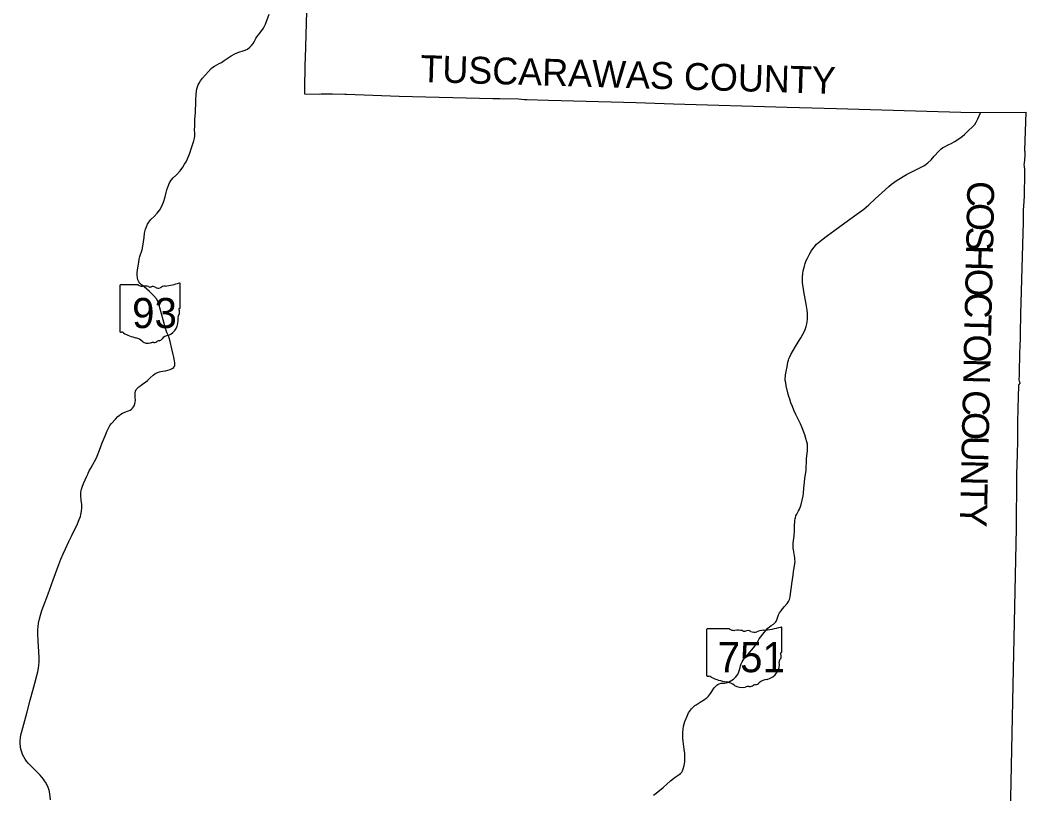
# Model space of a CAD drawing. Extents: x 2004415 to 2276415, y 751181 to 927181.
# Drawn here: x 2177346 to 2214759, y 838414 to 867212 of the extents above; entities that cross this region are included whole.
import ezdxf

# ---------------------------------------------------------------- set-up
doc = ezdxf.new("R2010")
doc.units = 0
for name, color, linetype in [('GM_X_County', 7, 'Continuous'), ('GM_X_County_Text', 7, 'Continuous'), ('GM_X_State_Location', 7, 'Continuous'), ('GM_X_State_Route', 7, 'Continuous'), ('GM_X_State_Shield', 7, 'Continuous')]:
    doc.layers.add(name, color=color, linetype=linetype)

msp = doc.modelspace()

# ---------------------------------------------------------------- linework, layer by layer
at = {"layer": 'GM_X_County'}
msp.add_lwpolyline([(2188009, 867975), (2187946, 865793), (2187943, 865563), (2187924, 864631), (2187921, 864465), (2188480, 864451), (2188549, 864467), (2188971, 864466), (2189427, 864451), (2189489, 864451), (2191444, 864380), (2194934, 864291), (2195070, 864290), (2195195, 864289), (2195884, 864276), (2196109, 864261), (2196154, 864260), (2196195, 864259), (2196999, 864238), (2200266, 864143), (2201652, 864100), (2205881, 863975), (2207719, 863920), (2212337, 863781), (2213068, 863770), (2214759, 863787), (2214712, 862361), (2214713, 862356), (2214726, 862318), (2214720, 862172), (2214712, 862011), (2214697, 861892), (2214689, 861834), (2214694, 861764), (2214704, 861652), (2214711, 861298), (2214695, 860899), (2214692, 860688), (2214680, 860444), (2214670, 860308), (2214664, 860127), (2214654, 860032), (2214655, 859699), (2214553, 856272), (2214557, 856218), (2214550, 855598), (2214546, 855462), (2214541, 855352), (2214528, 855120), (2214520, 854788), (2214518, 854552), (2214507, 854329), (2214505, 854132), (2214511, 853994), (2214501, 853822), (2214513, 853771), (2214537, 853723), (2214530, 853697), (2214491, 853649), (2214483, 853607), (2214483, 853542), (2214483, 853506), (2214474, 853287), (2214468, 853109), (2214458, 852828), (2214455, 852617), (2214452, 852373), (2214451, 852227), (2214446, 852103), (2214442, 851561), (2214438, 851040), (2214411, 850311), (2214412, 850218), (2214393, 848301), (2214324, 844793), (2214279, 842459), (2214173, 837662)], dxfattribs=at)
at = {"layer": 'GM_X_State_Route'}
for points in [[(2183864, 863756), (2183871, 863833), (2183883, 864126), (2183887, 864262), (2183894, 864435), (2183908, 864562), (2183925, 864659), (2183945, 864734), (2183972, 864808), (2184007, 864870), (2184055, 864947), (2184134, 865056), (2184349, 865304), (2184449, 865409), (2184513, 865461), (2184573, 865499), (2184662, 865547), (2184755, 865591), (2184832, 865635), (2184933, 865704), (2185086, 865812), (2185202, 865886), (2185332, 865958), (2185417, 865998), (2185507, 866033), (2185608, 866058), (2185713, 866092), (2185800, 866131), (2185894, 866199), (2185959, 866270), (2186018, 866346), (2186062, 866424), (2186114, 866525), (2186155, 866590), (2186213, 866662), (2186342, 866821), (2186405, 866913), (2186472, 867060), (2186526, 867197), (2186612, 867437)], [(2183067, 854300), (2183098, 854341), (2183103, 854383), (2183101, 854453), (2183090, 854535), (2183069, 854663), (2183044, 854772), (2182991, 854982), (2182931, 855250), (2182886, 855386), (2182848, 855481), (2182802, 855583), (2182757, 855733), (2182669, 856056), (2182609, 856277), (2182549, 856505), (2182505, 856671), (2182473, 856755), (2182420, 856838), (2182323, 856950), (2182156, 857116), (2182058, 857204), (2181965, 857282), (2181865, 857359), (2181801, 857418), (2181758, 857468), (2181726, 857547), (2181708, 857623), (2181698, 857715), (2181702, 857820), (2181724, 857991), (2181744, 858129), (2181757, 858205), (2181779, 858314), (2181805, 858410), (2181883, 858664), (2181912, 858795), (2181935, 858956), (2181955, 859118), (2181978, 859278), (2182010, 859428), (2182043, 859521), (2182088, 859613), (2182139, 859698), (2182211, 859787), (2182330, 859903), (2182448, 860027), (2182543, 860150), (2182605, 860259), (2182683, 860434), (2182743, 860635), (2182782, 860799), (2182805, 860896), (2182837, 861000), (2182875, 861095), (2182905, 861161), (2182968, 861252), (2183039, 861336), (2183160, 861458), (2183300, 861607), (2183401, 861739), (2183466, 861847), (2183521, 861939), (2183573, 862052), (2183654, 862259), (2183725, 862457), (2183811, 862718), (2183833, 862816), (2183842, 862901), (2183843, 862989), (2183839, 863139), (2183841, 863250), (2183844, 863411), (2183847, 863527), (2183864, 863756)], [(2200908, 838368), (2201005, 838441), (2201263, 838656), (2201538, 838895), (2201654, 838991), (2201716, 839036), (2201865, 839132), (2201914, 839171), (2201955, 839217), (2201989, 839275), (2202016, 839349), (2202046, 839466), (2202068, 839612), (2202077, 839726), (2202076, 839813), (2202069, 839913), (2202046, 840083), (2202010, 840372), (2201999, 840489), (2201998, 840608), (2202001, 840714), (2202012, 840810), (2202029, 840931), (2202051, 841024), (2202078, 841110), (2202158, 841311), (2202215, 841427), (2202247, 841478), (2202284, 841534), (2202322, 841584), (2202389, 841652), (2202448, 841702), (2202492, 841731), (2202646, 841823), (2202809, 841927), (2202866, 841971), (2202901, 842000), (2202952, 842052), (2203024, 842154), (2203164, 842362), (2203212, 842416), (2203259, 842457), (2203297, 842483), (2203351, 842509), (2203429, 842529), (2203486, 842531), (2203546, 842537), (2203605, 842546), (2203664, 842565), (2203756, 842604), (2203883, 842685), (2203934, 842728), (2203970, 842771), (2204020, 842834), (2204054, 842888), (2204098, 842996), (2204130, 843119), (2204161, 843225), (2204204, 843323), (2204246, 843395), (2204296, 843467), (2204410, 843603), (2204632, 843855), (2204718, 843956), (2204748, 843997), (2204781, 844049), (2204806, 844105), (2204842, 844183), (2204884, 844251), (2204968, 844353), (2205086, 844491), (2205166, 844579), (2205225, 844633), (2205281, 844676), (2205368, 844734), (2205421, 844778), (2205454, 844812), (2205483, 844858), (2205511, 844925), (2205538, 845002), (2205563, 845079), (2205600, 845156), (2205650, 845230), (2205711, 845306), (2205783, 845389), (2205880, 845499), (2205932, 845573), (2205967, 845652), (2205994, 845753), (2206007, 845856), (2206041, 846115), (2206055, 846228), (2206099, 846554), (2206119, 846694), (2206151, 846900), (2206164, 846992), (2206171, 847070), (2206170, 847126), (2206163, 847200), (2206149, 847277), (2206114, 847502), (2206107, 847565), (2206102, 847646), (2206107, 847730), (2206121, 847850), (2206137, 848003), (2206147, 848226), (2206156, 848464), (2206159, 848508), (2206165, 848599), (2206172, 848648), (2206185, 848694), (2206204, 848757), (2206234, 848820), (2206278, 848902), (2206303, 848949), (2206332, 849010), (2206374, 849113), (2206397, 849186), (2206438, 849345), (2206469, 849504), (2206482, 849603), (2206501, 849789), (2206521, 850010), (2206540, 850154), (2206576, 850392), (2206582, 850454), (2206588, 850562), (2206596, 850786), (2206601, 850901), (2206638, 851181), (2206641, 851284), (2206638, 851362), (2206630, 851427), (2206611, 851519), (2206576, 851643), (2206531, 851779), (2206435, 852036), (2206371, 852187), (2206313, 852311), (2206204, 852540), (2206129, 852698), (2206073, 852827), (2206020, 852968), (2205973, 853102), (2205941, 853198), (2205916, 853288), (2205844, 853606), (2205824, 853714), (2205810, 853802), (2205810, 853882), (2205814, 853943), (2205822, 854014), (2205845, 854131), (2205878, 854307), (2205908, 854482), (2205924, 854556), (2205939, 854604), (2205964, 854659), (2206018, 854761), (2206194, 855069), (2206391, 855391), (2206455, 855504), (2206507, 855606), (2206547, 855703), (2206583, 855814), (2206606, 855902), (2206620, 855986), (2206634, 856086), (2206639, 856188), (2206634, 856309), (2206623, 856414), (2206587, 856635), (2206534, 856911), (2206511, 857035), (2206482, 857196), (2206460, 857359), (2206452, 857450), (2206449, 857556), (2206451, 857641), (2206462, 857783), (2206480, 857880), (2206496, 857967), (2206519, 858052), (2206549, 858153), (2206589, 858259), (2206631, 858357), (2206667, 858431), (2206722, 858529), (2206775, 858614), (2206835, 858697), (2206886, 858761), (2206976, 858869), (2207094, 858978), (2207166, 859039), (2207374, 859193), (2207647, 859390), (2207975, 859630), (2208155, 859761), (2208471, 859985), (2208729, 860181), (2208916, 860341), (2209158, 860562), (2209401, 860779), (2209663, 861016), (2209758, 861100), (2209842, 861164), (2209975, 861253), (2210323, 861460), (2210587, 861602), (2210965, 861794), (2211054, 861849), (2211115, 861900), (2211236, 862015), (2211353, 862143), (2211518, 862337), (2211602, 862422), (2211657, 862458), (2211728, 862500), (2211871, 862569), (2211978, 862623), (2212114, 862698), (2212204, 862751), (2212336, 862846), (2212471, 862959), (2212642, 863116), (2212757, 863229), (2212856, 863331), (2212911, 863412), (2212978, 863540), (2213069, 863767)], [(2179609, 849649), (2179614, 849692), (2179626, 849755), (2179651, 849835), (2179704, 849966), (2179764, 850101), (2179831, 850242), (2179873, 850336), (2179881, 850354), (2179919, 850439), (2179980, 850540), (2180055, 850667), (2180159, 850870), (2180213, 850982), (2180298, 851212), (2180401, 851481), (2180508, 851746), (2180584, 851922), (2180643, 852044), (2180687, 852122), (2180742, 852200), (2180893, 852365), (2180978, 852454), (2181029, 852501), (2181096, 852550), (2181158, 852586), (2181236, 852623), (2181381, 852674), (2181434, 852698), (2181485, 852727), (2181532, 852768), (2181570, 852820), (2181591, 852854), (2181616, 852928), (2181631, 852991), (2181636, 853063), (2181630, 853163), (2181626, 853267), (2181627, 853345), (2181642, 853408), (2181666, 853464), (2181708, 853516), (2181758, 853560), (2181831, 853617), (2181917, 853676), (2182012, 853740), (2182090, 853803), (2182188, 853901), (2182292, 853996), (2182360, 854048), (2182454, 854096), (2182526, 854120), (2182582, 854135), (2182734, 854160)], [(2182734, 854160), (2182749, 854163), (2182845, 854184), (2182928, 854210), (2182999, 854245), (2183058, 854288), (2183067, 854300)], [(2178479, 838195), (2178449, 838422), (2178421, 838548), (2178391, 838646), (2178343, 838761), (2178290, 838854), (2178259, 838901), (2178216, 838960), (2178154, 839037), (2178091, 839107), (2177964, 839237), (2177776, 839425), (2177648, 839562), (2177589, 839632), (2177537, 839707), (2177484, 839796), (2177441, 839884), (2177410, 839966), (2177376, 840079), (2177359, 840166), (2177346, 840308), (2177350, 840407), (2177358, 840496), (2177377, 840610), (2177407, 840742), (2177592, 841418), (2177724, 841906), (2177896, 842537), (2177973, 842823), (2178006, 842959), (2178029, 843092), (2178043, 843203), (2178052, 843331), (2178055, 843489), (2178042, 843699), (2178015, 844116), (2178003, 844378), (2178004, 844525), (2178015, 844644), (2178032, 844770), (2178064, 844932), (2178099, 845061), (2178157, 845234), (2178276, 845559), (2178387, 845860), (2178576, 846378), (2178752, 846853), (2178866, 847148), (2178950, 847343), (2179035, 847534), (2179160, 847804), (2179268, 848034), (2179476, 848463), (2179546, 848625), (2179588, 848742), (2179608, 848815), (2179628, 848918), (2179637, 849069), (2179636, 849184), (2179621, 849342), (2179606, 849525), (2179605, 849612), (2179609, 849649)]]:
    msp.add_lwpolyline(points, dxfattribs=at)
at = {"layer": 'GM_X_State_Shield'}
for p, q in [((2181056, 857331), (2181056, 855630)), ((2181735, 857361), (2181078, 857361)), ((2183298, 856513), (2183298, 857403)), ((2183297, 856513), (2183298, 856513)), ((2202880, 844524), (2202880, 842823)), ((2203728, 844553), (2202907, 844553)), ((2205681, 843705), (2205681, 844595)), ((2205681, 843706), (2205681, 843705))]:
    msp.add_line(p, q, dxfattribs=at)
for centre, radius, start, end in [((2181082, 857335), 26, 98.1301, 188.1301), ((2181891, 857558), 252, 231.6195, 271.1119), ((2181975, 856406), 904, 80.4867, 94.9883), ((2182180, 857344), 72.7, 219.7921, 297.1024), ((2182287, 857147), 151, 54.4667, 119.1411), ((2182482, 857417), 182, 233.8562, 294.8282), ((2182802, 856841), 478, 97.3462, 120.7689), ((2182499, 859680), 2377, 275.8445, 288.9065), ((2183273, 857406), 25, 351.8621, 97.738), ((2183292, 856448), 38.6, 107.944, 210.337), ((2183046, 856335), 232, 340.033, 23.6496), ((2183271, 856509), 26.7, 289.6038, 7.7341), ((2182632, 856027), 595, 292.3089, 8.9858), ((2183387, 856140), 169, 136.8065, 186.9296), ((2181082, 855626), 26.2, 171.9584, 258.3066), ((2181086, 855800), 200, 267.339, 280.6039), ((2181127, 855532), 72.1, 29.7484, 93.2717), ((2182037, 857060), 1716, 240.4129, 257.1985), ((2181525, 854866), 537, 47.1842, 75.836), ((2182328, 855396), 182, 268.777, 315.5493), ((2182492, 855231), 51.1, 65.7517, 132.6484), ((2182471, 855465), 192, 282.8732, 323.2771), ((2182883, 855153), 326, 94.4031, 142.5768), ((2182106, 855524), 341, 230.7004, 286.2918), ((2182303, 854935), 280, 85.6951, 111.2099)]:
    msp.add_arc(centre, radius, start, end, dxfattribs=at)
for centre, major_axis, start_param, end_param in [((2202912, 844527), (32.5, 0), 1.712693, 3.28349), ((2203923, 844751), (315, 0), 4.042523, 4.731795), ((2204028, 843598), (1130, 0), 1.404758, 1.657858), ((2204284, 844536), (90.8, 0), 3.836095, 5.185415), ((2204417, 844340), (189, 0), 0.950623, 2.079405), ((2204661, 844609), (227, 0), 4.081561, 5.145723), ((2205062, 844034), (598, 0), 1.699011, 2.107814), ((2204683, 846872), (2971, 0), 4.814394, 5.042369), ((2205650, 844599), (31.2, 0), 6.141152, 7.989035), ((2205674, 843640), (48.3, 0), 1.883978, 3.671073), ((2205648, 843702), (33.4, 0), 5.05454, 6.418171), ((2204850, 843220), (743, 0), 5.101752, 6.440018), ((2205793, 843333), (211, 0), 2.387724, 3.262537), ((2205367, 843528), (290, 0), 5.934695, 6.695948), ((2202912, 842819), (32.7, 0), 3.00124, 4.508301), ((2202917, 842993), (250, 0), 4.665946, 4.897461), ((2202968, 842725), (90.1, 0), 0.519207, 1.627899), ((2204106, 844253), (2146, 0), 4.195997, 4.488961), ((2203466, 842058), (671, 0), 0.823519, 1.323587), ((2205163, 842345), (407, 0), 1.647645, 2.488434), ((2204192, 842716), (426, 0), 4.026481, 4.996735), ((2204438, 842128), (350, 0), 1.495662, 1.94098), ((2204469, 842589), (227, 0), 4.691044, 5.507374), ((2204675, 842424), (63.9, 0), 1.147584, 2.315152), ((2204648, 842658), (240, 0), 4.937069, 5.64225)]:
    msp.add_ellipse(centre, major_axis=major_axis, ratio=0.8, start_param=start_param, end_param=end_param, dxfattribs=at)

# ---------------------------------------------------------------- texts
at = {"layer": 'GM_X_County_Text'}
for s, rotation, p in [('TUSCARAWAS COUNTY', 358.3405, (2192224, 864911)), ('C', 269.2627, (2212581, 861226)), ('O', 268.9973, (2212570, 860414)), ('S', 268.856, (2212555, 859530)), ('H', 268.7559, (2212541, 858853)), ('O', 268.7124, (2212522, 857969)), ('C', 268.6908, (2212502, 857085)), ('T', 268.6961, (2212484, 856271)), ('O', 268.6928, (2212467, 855523)), ('N', 268.6954, (2212447, 854639)), ('C', 268.6964, (2212419, 853451)), ('O', 268.6928, (2212401, 852637)), ('U', 268.6954, (2212381, 851753)), ('N', 268.6928, (2212361, 850869)), ('T', 268.695, (2212340, 849985)), ('Y', 268.6954, (2212323, 849237))]:
    msp.add_text(s, height=1000, rotation=rotation, dxfattribs=at).set_placement(p)
at = {"layer": 'GM_X_State_Location'}
for s, p in [('93', (2182334, 856687)), ('751', (2204206, 843426))]:
    msp.add_text(s, height=1, rotation=0, dxfattribs=at).set_placement(p)
for s, p in [('s', (2182586, 856760)), ('r', (2182586, 856760)), ('s', (2204559, 843498)), ('r', (2204559, 843498))]:
    msp.add_text(s, height=1, dxfattribs=at).set_placement(p)
at = {"layer": 'GM_X_State_Shield'}
for s, p in [('93', (2181512, 855750)), ('751', (2203293, 842943))]:
    msp.add_text(s, height=1120.7, dxfattribs=at).set_placement(p)

doc.saveas('drawing.dxf')
